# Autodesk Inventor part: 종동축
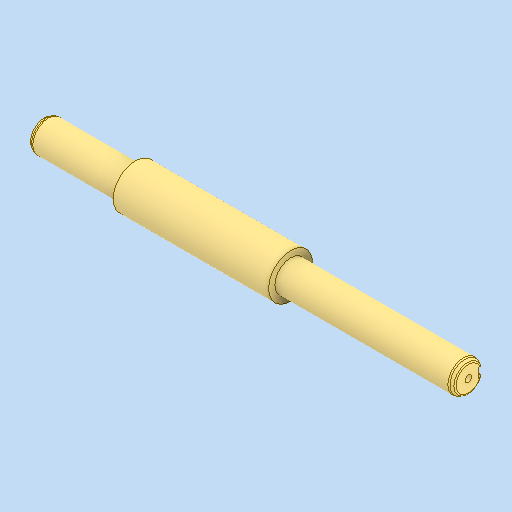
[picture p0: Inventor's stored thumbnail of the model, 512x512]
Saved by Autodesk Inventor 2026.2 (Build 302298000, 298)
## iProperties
Created: 2026-01
Part Number: 종동축
Material: 강철, 탄소
Document SubType Name: Modeling
Designer: PC2-07
Density: 7.85 g/cm^3
Appearance: 기본값
Author: jhkim
Sending System: Autodesk Inventor 2026
Preprocessor: ST-DEVELOPER v20.1
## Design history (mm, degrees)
feature "솔리드1"
node "솔리드2"
